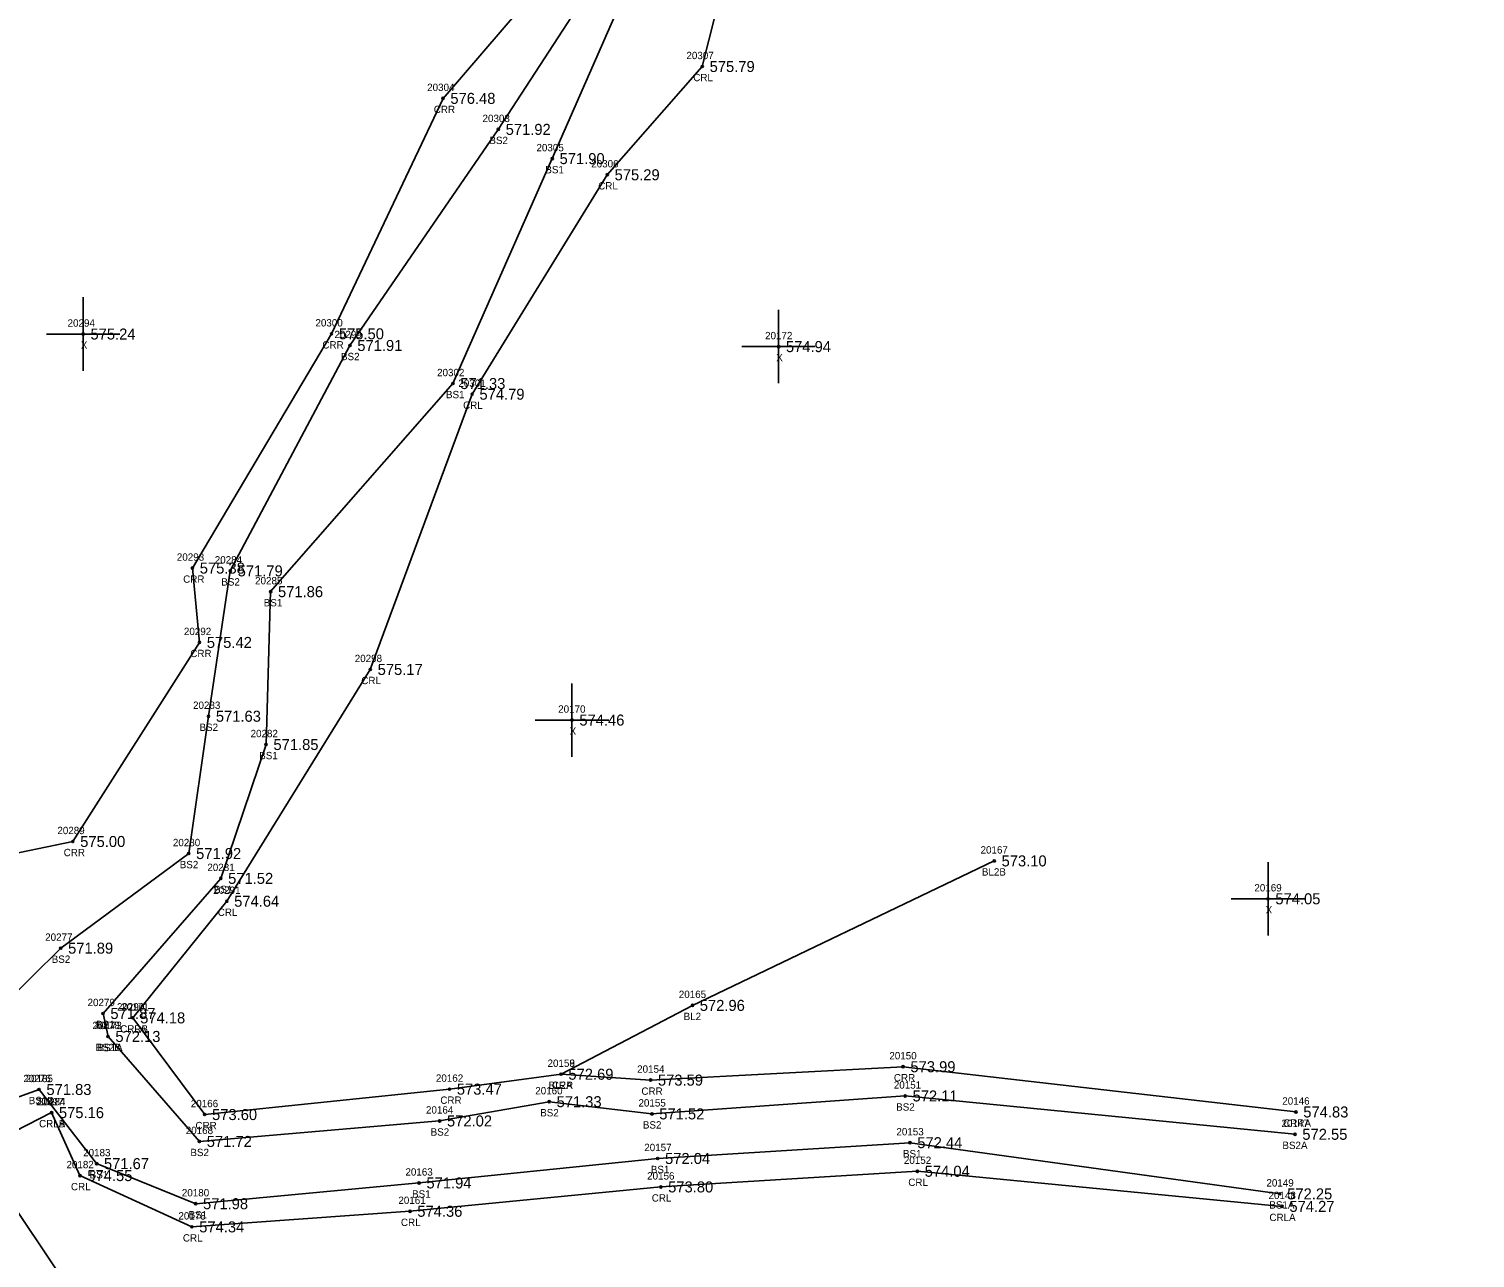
# Model space of a CAD drawing. Extents: x 1664837 to 1666270, y 987403 to 988245.
# Drawn here: x 1665562.6 to 1665759.5, y 987773 to 987940.3 of the extents above; entities that cross this region are included whole.
import ezdxf

# ---------------------------------------------------------------- set-up
doc = ezdxf.new("R2010")
doc.units = 0
for name, color, linetype in [('RD_DTM_BkLn1', 7, 'Continuous'), ('RD_DTM_BkLn2', 7, 'Continuous'), ('RD_DTM_BkLn_txCode', 7, 'Continuous'), ('RD_EX_H2O', 7, 'Continuous'), ('RD_EX_H2O_txCode', 7, 'Continuous'), ('RD_EX_Misc', 7, 'Continuous'), ('RD_EX_Misc_txCode', 7, 'Continuous'), ('RD_EX_TX_H2O_ELEV', 7, 'Continuous'), ('RD_EX_TX_Misc_ELEV', 7, 'Continuous'), ('RD_SMD_Locator', 7, 'Continuous')]:
    doc.layers.add(name, color=color, linetype=linetype)

msp = doc.modelspace()

# ---------------------------------------------------------------- linework, layer by layer
at = {"layer": 'RD_DTM_BkLn1'}
msp.add_lwpolyline([(1665635.06, 987798.01), (1665652.95, 987807.38), (1665694.04, 987827.05)], dxfattribs=at)
at = {"layer": 'RD_DTM_BkLn2'}
for points in [[(1665511.23, 987778.14), (1665517.66, 987789.45), (1665551.13, 987799.55), (1665566.94, 987815.17), (1665584.37, 987828.05), (1665587.06, 987846.74), (1665590.03, 987866.53), (1665606.32, 987897.21), (1665626.52, 987926.63), (1665648.51, 987960.46), (1665641.85, 987993.37), (1665649.56, 988007.84), (1665641.39, 988045.42), (1665662.4, 988073.33), (1665687.13, 988124.22), (1665718.46, 988169.29), (1665714.8, 988227.5)], [(1665573.38, 987803.15), (1665572.7, 987806.28), (1665588.73, 987824.67), (1665594.9, 987842.89), (1665595.52, 987863.7), (1665620.34, 987892.03), (1665633.86, 987922.65), (1665655.32, 987971.56), (1665650.57, 987994.06), (1665655.98, 988006.97), (1665652.16, 988045.8), (1665666.56, 988071.61), (1665695.3, 988121.96), (1665722.67, 988165.82), (1665720.98, 988226.06)], [(1665734.99, 987789.83), (1665681.92, 987795.05), (1665647.43, 987792.61), (1665633.45, 987794.27), (1665618.53, 987791.65), (1665585.82, 987788.86), (1665573.38, 987803.15)], [(1665521.8, 987775.03), (1665533.32, 987783.17), (1665553.38, 987792.14), (1665563.99, 987795.93)], [(1665732.93, 987781.72), (1665682.56, 987788.69), (1665648.22, 987786.54), (1665615.73, 987783.21), (1665585.31, 987780.38), (1665571.82, 987785.84), (1665563.99, 987795.93)], [(1665937.25, 987616.34), (1665889.99, 987630.17), (1665844.42, 987647.08), (1665801.11, 987667.84), (1665753.91, 987686.95), (1665707.93, 987709.21), (1665661.99, 987726.38), (1665615.37, 987748.93), (1665567.93, 987769.01), (1665555.48, 987787.59)]]:
    msp.add_lwpolyline(points, dxfattribs=at)
at = {"layer": 'RD_EX_H2O'}
for points in [[(1665526.5, 987797.57), (1665535.59, 987808.2), (1665547.98, 987825.42), (1665568.59, 987829.69), (1665585.83, 987856.79), (1665584.87, 987866.91), (1665603.81, 987898.8), (1665618.99, 987930.85), (1665645.33, 987961.5), (1665639.67, 987994.37), (1665644.94, 988008.07), (1665639.5, 988048.94), (1665653.76, 988079.25), (1665684.31, 988124.82), (1665706.22, 988174.88), (1665711.8, 988227.54)], [(1665576.75, 987805.68), (1665589.55, 987821.56), (1665609.09, 987853.11), (1665622.95, 987890.58), (1665641.35, 987920.45), (1665654.29, 987935.19), (1665658.75, 987952.97), (1665657.67, 987971.74), (1665650.8, 987993.69), (1665662.98, 988008.61), (1665660.68, 988035.04), (1665652.89, 988045.21), (1665674.32, 988062.08), (1665698.86, 988119.64), (1665728.36, 988166.73), (1665725.83, 988226.06)], [(1665735.12, 987792.87), (1665681.63, 987799.03), (1665647.25, 987797.21), (1665635.06, 987798.01), (1665619.87, 987795.98), (1665586.54, 987792.52), (1665576.75, 987805.68)], [(1665565.69, 987792.78), (1665555.48, 987787.59), (1665542.58, 987772.17), (1665532.86, 987767.81), (1665532.86, 987767.81), (1665531.47, 987764.82)], [(1665733.23, 987780.02), (1665683.57, 987784.8), (1665648.64, 987782.67), (1665614.49, 987779.35), (1665584.79, 987777.23), (1665569.56, 987784.21), (1665565.69, 987792.78)]]:
    msp.add_lwpolyline(points, dxfattribs=at)
at = {"layer": 'RD_EX_Misc'}
for p, q in [((1665569.99, 987893.77), (1665569.99, 987903.77)), ((1665664.68, 987892.06), (1665664.68, 987902.06)), ((1665564.99, 987898.77), (1665574.99, 987898.77)), ((1665659.68, 987897.06), (1665669.68, 987897.06)), ((1665636.55, 987841.22), (1665636.55, 987851.22)), ((1665631.55, 987846.22), (1665641.55, 987846.22)), ((1665731.32, 987816.89), (1665731.32, 987826.89)), ((1665726.32, 987821.89), (1665736.32, 987821.89))]:
    msp.add_line(p, q, dxfattribs=at)
at = {"layer": 'RD_SMD_Locator'}
for centre in [(1665654.29, 987935.19), (1665618.99, 987930.85), (1665626.52, 987926.63), (1665633.86, 987922.65), (1665641.35, 987920.45), (1665569.99, 987898.77), (1665603.81, 987898.8), (1665606.32, 987897.21), (1665664.68, 987897.06), (1665620.34, 987892.03), (1665622.95, 987890.58), (1665584.87, 987866.91), (1665590.03, 987866.53), (1665595.52, 987863.7), (1665585.83, 987856.79), (1665609.09, 987853.11), (1665587.06, 987846.74), (1665636.55, 987846.22), (1665594.9, 987842.89), (1665568.59, 987829.69), (1665584.37, 987828.05), (1665694.04, 987827.05), (1665588.73, 987824.67), (1665589.55, 987821.56), (1665731.32, 987821.89), (1665566.94, 987815.17), (1665652.95, 987807.38), (1665572.7, 987806.28), (1665576.75, 987805.68), (1665576.75, 987805.68), (1665573.38, 987803.15), (1665573.38, 987803.15), (1665681.63, 987799.03), (1665635.06, 987798.01), (1665635.06, 987798.01), (1665647.25, 987797.21), (1665563.99, 987795.93), (1665563.99, 987795.93), (1665619.87, 987795.98), (1665681.92, 987795.05), (1665565.69, 987792.78), (1665565.69, 987792.78), (1665633.45, 987794.27), (1665647.43, 987792.61), (1665735.12, 987792.87), (1665586.54, 987792.52), (1665618.53, 987791.65), (1665585.82, 987788.86), (1665682.56, 987788.69), (1665734.99, 987789.83), (1665571.82, 987785.84), (1665648.22, 987786.54), (1665683.57, 987784.8), (1665569.56, 987784.21), (1665615.73, 987783.21), (1665648.64, 987782.67), (1665732.93, 987781.72), (1665585.31, 987780.38), (1665614.49, 987779.35), (1665733.23, 987780.02), (1665584.79, 987777.23)]:
    msp.add_circle(centre, 0.15, dxfattribs=at)

# ---------------------------------------------------------------- texts
at = {"layer": 'RD_DTM_BkLn_txCode'}
for s, p in [('20303', (1665624.37, 987927.63)), ('BS2', (1665625.3, 987924.63)), ('20305', (1665631.71, 987923.65)), ('BS1', (1665632.92, 987920.65)), ('20299', (1665604.21, 987898.21)), ('BS2', (1665605.1, 987895.21)), ('20302', (1665618.18, 987893.03)), ('BS1', (1665619.39, 987890.03)), ('20284', (1665587.91, 987867.53)), ('BS2', (1665588.8, 987864.53)), ('20285', (1665593.4, 987864.7)), ('BS1', (1665594.58, 987861.7)), ('20283', (1665584.95, 987847.74)), ('BS2', (1665585.83, 987844.74)), ('20282', (1665592.79, 987843.89)), ('BS1', (1665593.96, 987840.89)), ('20280', (1665582.21, 987829.05)), ('20167', (1665692.18, 987828.05)), ('BS2', (1665583.14, 987826.05)), ('20281', (1665586.9, 987825.67)), ('BL2B', (1665692.36, 987825.05)), ('BS1', (1665587.79, 987822.67)), ('20277', (1665564.82, 987816.17)), ('BS2', (1665565.71, 987813.17)), ('20165', (1665651.09, 987808.38)), ('20279', (1665570.59, 987807.28)), ('20278', (1665571.26, 987804.15)), ('20173', (1665571.54, 987804.15)), ('BS1', (1665571.76, 987804.28)), ('BL2', (1665651.75, 987805.38)), ('BS2B', (1665571.68, 987801.15)), ('BS1A', (1665571.94, 987801.15)), ('20159', (1665633.22, 987799.01)), ('20276', (1665561.85, 987796.93)), ('20185', (1665562.16, 987796.93)), ('BL2A', (1665633.36, 987796.01)), ('20151', (1665680.37, 987796.05)), ('BS1B', (1665562.58, 987793.93)), ('BS1B', (1665562.58, 987793.93)), ('20160', (1665631.55, 987795.27)), ('20164', (1665616.67, 987792.65)), ('BS2', (1665632.22, 987792.27)), ('20155', (1665645.6, 987793.61)), ('BS2', (1665680.69, 987793.05)), ('20168', (1665583.96, 987789.86)), ('BS2', (1665646.2, 987790.61)), ('20147', (1665733.16, 987790.83)), ('BS2', (1665617.3, 987789.65)), ('20153', (1665680.72, 987789.69)), ('BS2A', (1665733.28, 987787.83)), ('20183', (1665569.99, 987786.84)), ('BS2', (1665584.59, 987786.86)), ('20157', (1665646.39, 987787.54)), ('BS1', (1665681.61, 987786.69)), ('BS1', (1665570.88, 987783.84)), ('20163', (1665613.87, 987784.21)), ('BS1', (1665647.28, 987784.54)), ('20149', (1665731.1, 987782.72)), ('20180', (1665583.43, 987781.38)), ('BS1', (1665614.78, 987781.21)), ('BS1', (1665584.36, 987778.38)), ('BS1A', (1665731.5, 987779.72))]:
    msp.add_text(s, height=1, dxfattribs=at).set_placement(p)
at = {"layer": 'RD_EX_H2O_txCode'}
for s, p in [('20307', (1665652.13, 987936.19)), ('20304', (1665616.83, 987931.85)), ('CRL', (1665653.06, 987933.19)), ('CRR', (1665617.73, 987928.85)), ('20306', (1665639.17, 987921.45)), ('CRL', (1665640.12, 987918.45)), ('20300', (1665601.62, 987899.8)), ('CRR', (1665602.56, 987896.8)), ('20301', (1665621.08, 987891.58)), ('CRL', (1665621.72, 987888.58)), ('20293', (1665582.75, 987867.91)), ('CRR', (1665583.61, 987864.91)), ('20292', (1665583.71, 987857.79)), ('CRR', (1665584.58, 987854.79)), ('20298', (1665606.97, 987854.11)), ('CRL', (1665607.86, 987851.11)), ('20289', (1665566.48, 987830.69)), ('CRR', (1665567.34, 987827.69)), ('20291', (1665587.71, 987822.56)), ('CRL', (1665588.32, 987819.56)), ('20290', (1665574.6, 987806.68)), ('20171', (1665575.2, 987806.68)), ('CRRB', (1665575.03, 987803.68)), ('CRLA', (1665575.04, 987803.68)), ('20150', (1665679.76, 987800.03)), ('20158', (1665633.22, 987799.01)), ('20154', (1665645.42, 987798.21)), ('20162', (1665618.02, 987796.98)), ('CRR', (1665633.81, 987796.01)), ('CRR', (1665680.38, 987797.03)), ('20397', (1665563.58, 987793.78)), ('20184', (1665563.86, 987793.78)), ('CRR', (1665618.62, 987793.98)), ('CRR', (1665646, 987795.21)), ('20146', (1665733.26, 987793.87)), ('20166', (1665584.65, 987793.52)), ('CRLA', (1665563.98, 987790.78)), ('CRLB', (1665563.99, 987790.78)), ('CRR', (1665585.28, 987790.52)), ('CRRA', (1665733.38, 987790.87)), ('20152', (1665681.74, 987785.8)), ('20182', (1665567.72, 987785.21)), ('CRL', (1665568.33, 987782.21)), ('20156', (1665646.78, 987783.67)), ('CRL', (1665682.34, 987782.8)), ('20161', (1665612.91, 987780.35)), ('CRL', (1665647.41, 987780.67)), ('20148', (1665731.39, 987781.02)), ('20178', (1665582.96, 987778.23)), ('CRLA', (1665731.51, 987778.02)), ('CRL', (1665613.26, 987777.35)), ('CRL', (1665583.57, 987775.23))]:
    msp.add_text(s, height=1, dxfattribs=at).set_placement(p)
at = {"layer": 'RD_EX_Misc_txCode'}
for s, p in [('20294', (1665567.87, 987899.77)), ('20172', (1665662.84, 987898.06)), ('X', (1665569.67, 987896.77)), ('X', (1665664.36, 987895.06)), ('20170', (1665634.67, 987847.22)), ('X', (1665636.23, 987844.22)), ('20169', (1665729.46, 987822.89)), ('X', (1665731, 987819.89))]:
    msp.add_text(s, height=1, dxfattribs=at).set_placement(p)
at = {"layer": 'RD_EX_TX_H2O_ELEV'}
for s, p in [('575.79', (1665655.29, 987934.44)), ('576.48', (1665619.99, 987930.1)), ('575.29', (1665642.35, 987919.7)), ('575.50', (1665604.81, 987898.05)), ('574.79', (1665623.95, 987889.83)), ('575.38', (1665585.87, 987866.16)), ('575.42', (1665586.83, 987856.04)), ('575.17', (1665610.09, 987852.36)), ('575.00', (1665569.59, 987828.94)), ('574.64', (1665590.55, 987820.81)), ('574.18', (1665577.75, 987804.93)), ('574.18', (1665577.75, 987804.93)), ('572.69', (1665636.06, 987797.26)), ('573.99', (1665682.63, 987798.28)), ('573.47', (1665620.87, 987795.23)), ('573.59', (1665648.25, 987796.46)), ('575.16', (1665566.69, 987792.03)), ('575.16', (1665566.69, 987792.03)), ('573.60', (1665587.54, 987791.77)), ('574.83', (1665736.12, 987792.12)), ('574.55', (1665570.56, 987783.46)), ('574.04', (1665684.57, 987784.05)), ('573.80', (1665649.64, 987781.92)), ('574.36', (1665615.49, 987778.6)), ('574.27', (1665734.23, 987779.27)), ('574.34', (1665585.79, 987776.48))]:
    msp.add_text(s, height=1.5, dxfattribs=at).set_placement(p)
at = {"layer": 'RD_EX_TX_Misc_ELEV'}
for s, p in [('571.92', (1665627.52, 987925.88)), ('571.90', (1665634.86, 987921.9)), ('575.24', (1665570.99, 987898.02)), ('571.91', (1665607.32, 987896.46)), ('574.94', (1665665.68, 987896.31)), ('571.33', (1665621.34, 987891.28)), ('571.79', (1665591.03, 987865.78)), ('571.86', (1665596.52, 987862.95)), ('571.63', (1665588.06, 987845.99)), ('574.46', (1665637.55, 987845.47)), ('571.85', (1665595.9, 987842.14)), ('571.92', (1665585.37, 987827.3)), ('573.10', (1665695.04, 987826.3)), ('571.52', (1665589.73, 987823.92)), ('574.05', (1665732.32, 987821.14)), ('571.89', (1665567.94, 987814.42)), ('571.87', (1665573.7, 987805.53)), ('572.96', (1665653.95, 987806.63)), ('572.13', (1665574.38, 987802.4)), ('572.13', (1665574.38, 987802.4)), ('572.69', (1665636.06, 987797.26)), ('571.83', (1665564.99, 987795.18)), ('571.83', (1665564.99, 987795.18)), ('571.33', (1665634.45, 987793.52)), ('572.11', (1665682.92, 987794.3)), ('571.52', (1665648.43, 987791.86)), ('572.02', (1665619.53, 987790.9)), ('571.72', (1665586.82, 987788.11)), ('572.44', (1665683.56, 987787.94)), ('572.55', (1665735.99, 987789.08)), ('572.04', (1665649.22, 987785.79)), ('571.67', (1665572.82, 987785.09)), ('571.94', (1665616.73, 987782.46)), ('571.98', (1665586.31, 987779.63)), ('572.25', (1665733.93, 987780.97))]:
    msp.add_text(s, height=1.5, dxfattribs=at).set_placement(p)

doc.saveas('drawing.dxf')
